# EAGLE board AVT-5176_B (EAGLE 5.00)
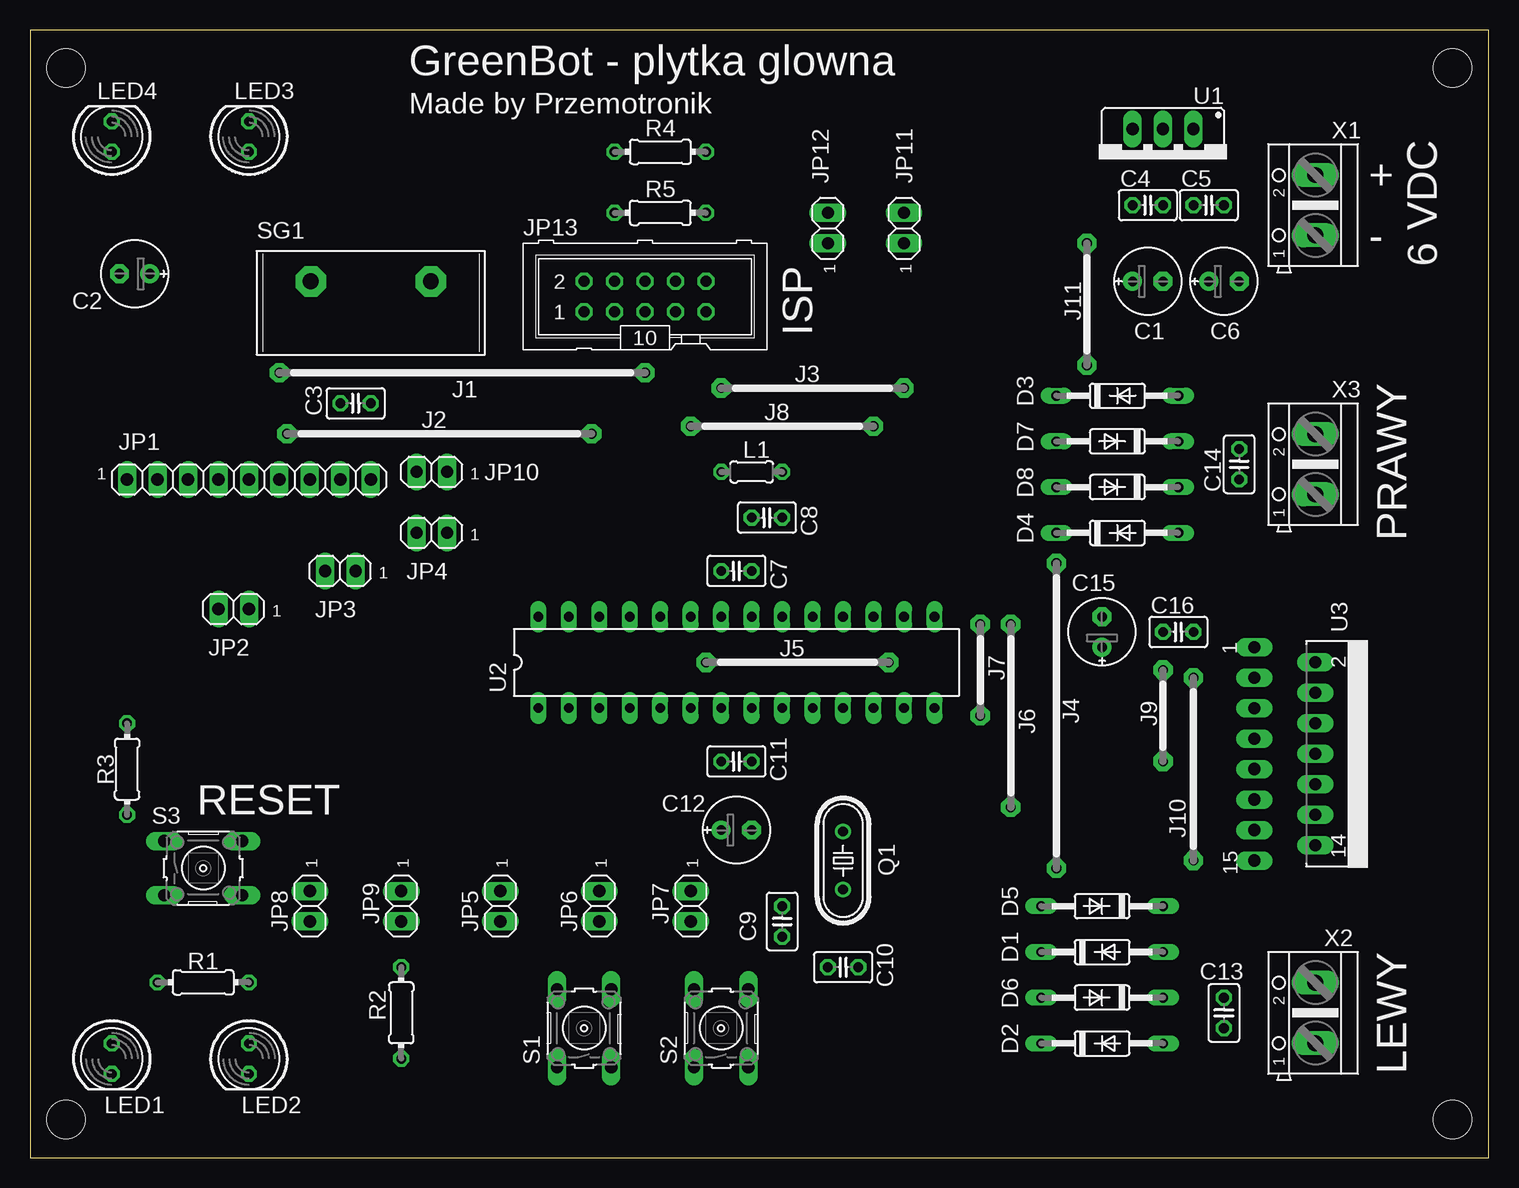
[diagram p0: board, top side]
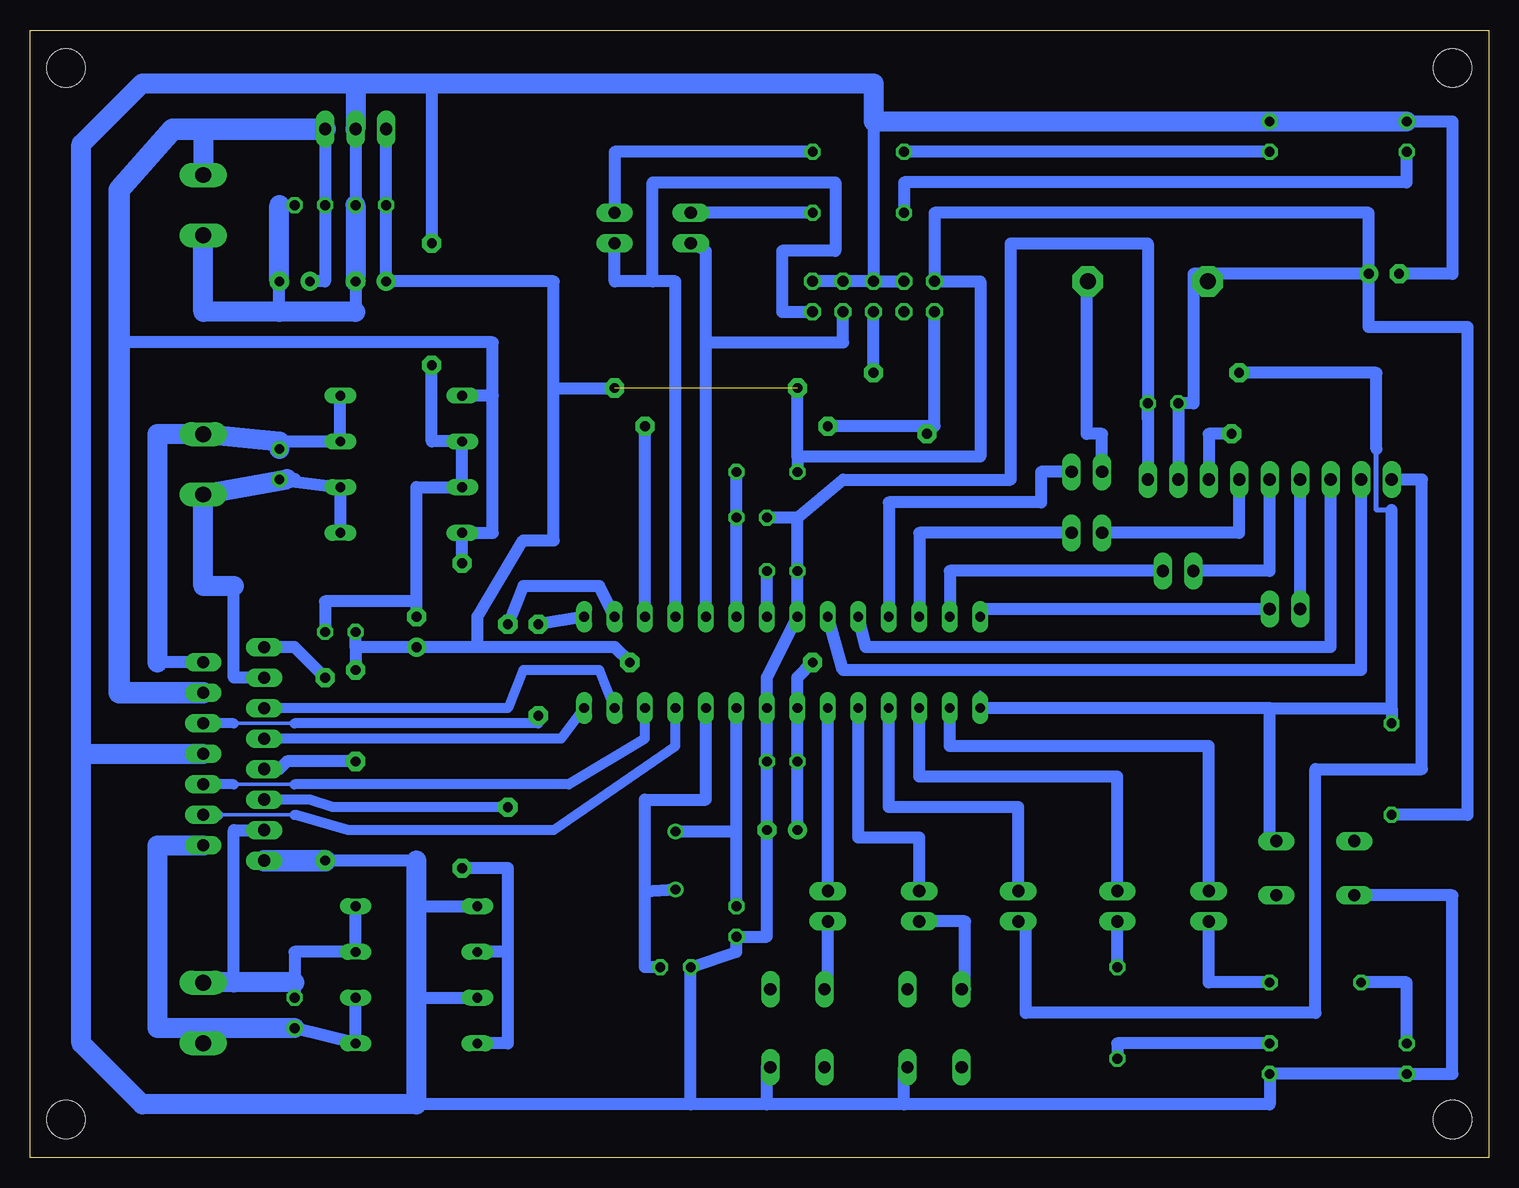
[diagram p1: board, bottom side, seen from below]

Size 121.59 x 93.97 mm. Coordinates in mm from the lower left corner, seen from the top.
Outline: 0,0 121.59,0 121.59,93.97 0,93.97 0,0
Copper layers (1*16): Top 0.035mm / dielectric 1.5mm / Bottom 0.035mm
Design rules "default": minimum track width 10mil, minimum drill 24mil, track to track 8mil, track to pad 8mil, pad to pad 8mil, via to via 8mil, smd to smd 8mil, copper to edge 40mil, drill to drill 8mil, minimum pad ring 10mil, minimum via ring 8mil, stop-mask expansion 4mil, vias tented up to drill 0mil, thermal gap 10mil
Holes 3.2 mm at 3.01,90.8 3.01,3.17 118.58,90.8 118.58,3.17

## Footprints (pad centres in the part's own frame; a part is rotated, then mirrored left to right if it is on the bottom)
E2,5-6E = drill 0.813 pad 1.575 round: + -1.27,0 | drill 0.813 pad 1.575 octagon: - 1.27,0
C025-025X050 = drill 0.813 octagon: 1 -1.27,0; 2 1.27,0
DO35-10 = drill 0.813 long: A 5.08,0; C -5.08,0
30 = drill 0.813 pad 1.6 octagon: 1 -15.24,0; 2 15.24,0
25 = drill 0.813 pad 1.6 octagon: 1 -12.7,0; 2 12.7,0
15 = drill 0.813 pad 1.6 octagon: 1 -7.62,0; 2 7.62,0
07 = drill 0.813 pad 1.6 octagon: 1 -3.81,0; 2 3.81,0
10 = drill 0.813 pad 1.6 octagon: 1 -5.08,0; 2 5.08,0
1X09 = drill 1.016 long: 1 -10.16,0; 2 -7.62,0; 3 -5.08,0; 4 -2.54,0; 5 0,0; 6 2.54,0; 7 5.08,0; 8 7.62,0; 9 10.16,0
1X02 = drill 1.016 long: 1 -1.27,0; 2 1.27,0
ML10 = drill 0.914 octagon: 1 -5.08,-1.27; 2 -5.08,1.27; 3 -2.54,-1.27; 4 -2.54,1.27; 5 0,-1.27; 6 0,1.27; 7 2.54,-1.27; 8 2.54,1.27; 9 5.08,-1.27; 10 5.08,1.27
0204/5 = drill 0.813 octagon: 1 -2.54,0; 2 2.54,0
LED5MM = drill 0.813 octagon: A -1.27,0; K 1.27,0
HC49/S = drill 0.813 round: 1 -2.413,0; 2 2.413,0
0204/7 = drill 0.813 octagon: 1 -3.81,0; 2 3.81,0
B3F-10XX = drill 1.016 long: 1 -3.251,2.261; 2 3.251,2.261; 3 -3.251,-2.261; 4 3.251,-2.261
B/C14S = drill 1.321 pad 2.54 octagon: 1 -5.004,0; 2 5.004,0
78XXS = drill 1.016 long: GND 0,-2.54; IN -2.54,-2.54; OUT 2.54,-2.54
DIL28-3 = drill 0.813 long: 1 -16.51,-3.81; 2 -13.97,-3.81; 3 -11.43,-3.81; 4 -8.89,-3.81; 5 -6.35,-3.81; 6 -3.81,-3.81; 7 -1.27,-3.81; 8 1.27,-3.81; 9 3.81,-3.81; 10 6.35,-3.81; 11 8.89,-3.81; 12 11.43,-3.81; 13 13.97,-3.81; 14 16.51,-3.81; 15 16.51,3.81; 16 13.97,3.81; 17 11.43,3.81; 18 8.89,3.81; 19 6.35,3.81; 20 3.81,3.81; 21 1.27,3.81; 22 -1.27,3.81; 23 -3.81,3.81; 24 -6.35,3.81; 25 -8.89,3.81; 26 -11.43,3.81; 27 -13.97,3.81; 28 -16.51,3.81
MULTIWATT-15 = drill 1.016 long: 1 -8.89,-7.62; 2 -7.62,-2.54; 3 -6.35,-7.62; 4 -5.08,-2.54; 5 -3.81,-7.62; 6 -2.54,-2.54; 7 -1.27,-7.62; 8 0,-2.54; 9 1.27,-7.62; 10 2.54,-2.54; 11 3.81,-7.62; 12 5.08,-2.54; 13 6.35,-7.62; 14 7.62,-2.54; 15 8.89,-7.62
AK500/2 = drill 1.321 long: 1 -2.515,0; 2 2.515,0

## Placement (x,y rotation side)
C1  100uF  [E2,5-6E]  93.18,73.02 0 top
C2  100uF  [E2,5-6E]  8.72,73.65 180 top
C3  100nF  [C025-025X050]  27.14,62.86 0 top
C4  100nF  [C025-025X050]  93.18,79.37 0 top
C5  100nF  [C025-025X050]  98.26,79.37 0 top
C6  100uF  [E2,5-6E]  99.53,73.02 0 top
C7  100nF  [C025-025X050]  58.89,48.89 180 top
C8  100nF  [C025-025X050]  61.43,53.34 180 top
C9  33pF  [C025-025X050]  62.7,19.68 90 top
C10  33pF  [C025-025X050]  67.78,15.87 0 top
C11  100nF  [C025-025X050]  58.89,33.02 180 top
C12  100uF  [E2,5-6E]  58.89,27.3 0 top
C13  100nF  [C025-025X050]  99.53,12.06 90 top
C14  100nF  [C025-025X050]  100.8,57.78 90 top
C15  100uF  [E2,5-6E]  89.37,43.81 90 top
C16  100nF  [C025-025X050]  95.72,43.81 0 top
D1  BYV26E  [DO35-10]  89.37,17.14 0 top
D2  BYV26E  [DO35-10]  89.37,9.52 0 top
D3  BYV26E  [DO35-10]  90.64,63.49 0 top
D4  BYV26E  [DO35-10]  90.64,52.06 0 top
D5  BYV26E  [DO35-10]  89.37,20.95 180 top
D6  BYV26E  [DO35-10]  89.37,13.33 180 top
D7  BYV26E  [DO35-10]  90.64,59.69 180 top
D8  BYV26E  [DO35-10]  90.64,55.88 180 top
J1  J30MM  [30]  36.03,65.4 180 top
J2  J25MM  [25]  34.12,60.32 180 top
J3  J15MM  [15]  65.24,64.13 180 top
J4  J25MM  [25]  85.56,36.82 90 top
J5  J15MM  [15]  63.97,41.27 180 top
J6  J15MM  [15]  81.75,36.82 270 top
J7  J7MM  [07]  79.21,40.63 270 top
J8  J15MM  [15]  62.7,60.95 180 top
J9  J7MM  [07]  94.45,36.82 270 top
J10  J15MM  [15]  96.99,32.38 90 top
J11  J10MM  [10]  88.1,71.11 270 top
JP1  [1X09]  18.25,56.51 0 top
JP2  [1X02]  16.98,45.72 180 top
JP3  [1X02]  25.87,48.89 180 top
JP4  [1X02]  33.49,52.06 180 top
JP5  [1X02]  39.2,20.95 270 top
JP6  [1X02]  47.46,20.95 270 top
JP7  [1X02]  55.08,20.95 270 top
JP8  [1X02]  23.33,20.95 270 top
JP9  [1X02]  30.95,20.95 270 top
JP10  [1X02]  33.49,57.15 180 top
JP11  [1X02]  72.86,77.46 90 top
JP12  [1X02]  66.51,77.46 90 top
JP13  AVR-ISP-10ML  [ML10]  51.27,71.75 0 top
L1  10uH  [0204/5]  60.16,57.15 0 top
LED1  R 5mm  [LED5MM]  6.82,8.25 270 top
LED2  G 5mm  [LED5MM]  18.25,8.25 270 top
LED3  R 5mm  [LED5MM]  18.25,85.08 90 top
LED4  G 5mm  [LED5MM]  6.82,85.08 90 top
Q1  8MHz  [HC49/S]  67.78,24.76 90 top
R1  220R  [0204/7]  14.44,14.6 180 top
R2  220R  [0204/7]  30.95,12.06 90 top
R3  1k  [0204/7]  8.09,32.38 270 top
R4  220R  [0204/7]  52.54,83.81 180 top
R5  220R  [0204/7]  52.54,78.73 0 top
S1  uSwitch  [B3F-10XX]  46.19,10.79 90 top
S2  uSwitch  [B3F-10XX]  57.62,10.79 90 top
S3  uSwitch  [B3F-10XX]  14.44,24.12 0 top
SG1  Piezzo z gen.  [B/C14S]  28.41,73.02 0 top
U1  L4940V05  [78XXS]  94.45,83.18 180 top
U2  MEGA8-P  [DIL28-3]  58.89,41.27 0 top
U3  L298  [MULTIWATT-15]  109.69,33.65 270 top
X1  ARK2  [AK500/2]  107.15,79.37 90 top
X2  ARK2  [AK500/2]  107.15,12.06 90 top
X3  ARK2  [AK500/2]  107.15,57.78 90 top

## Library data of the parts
C1-C16 L1 R1-R5 = rcl
D1-D8 = diode
J1-J11 = jumper
JP1-JP12 = pinhead
JP13 = atmel-1
LED1-LED4 = led
Q1 = crystal
S1-S3 = switch-omron
SG1 = buzzer
U1 = v-reg
U2 = atmel
U3 = st-microelectronics
X1-X3 = con-ptr500

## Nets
+5V: C1.+ C2.+ C3.1 C4.1 C15.+ C16.1 J3.1 J3.2 J5.1 J9.1 JP1.8 JP13.2 L1.1 R3.2 SG1.1 U1.OUT
GND: C1.- C2.- C3.2 C4.2 C5.2 C6.- C7.2 C8.2 C9.1 C10.1 C11.1 C12.- D5.A D6.A J10.1 J11.1 JP1.9 JP13.4 JP13.6 JP13.8 JP13.10 LED1.K LED2.K LED3.K LED4.K S1.3 S2.3 S3.3 U1.GND U2.8 U2.22 U3.8 U3.15 X1.1
N$1: JP10.2 SG1.2
N$2: C7.1 U2.21
N$3: C5.1 C6.+ D3.C D4.C J4.2 U1.IN U3.4 X1.2
N$4: C9.2 Q1.2 U2.9
N$5: C10.2 Q1.1 U2.10
N$6: JP10.1 U2.25
N$7: JP11.1 JP13.9 U2.18
N$8: LED3.A R4.2
N$9: JP8.2 R1.1
N$10: J6.1 U2.16
N$11: C8.1 L1.2 U2.20
N$12: JP1.2 U2.23
N$13: JP1.1 JP5.2
N$14: JP11.2 R4.1
N$15: J1.1 JP13.5
N$16: JP12.2 R5.2
N$17: JP1.6 JP4.2
N$18: JP1.3 U2.24
N$19: J6.2 U3.11
N$20: JP9.2 R2.2
N$21: JP1.5 JP3.2
N$22: JP1.4 JP2.2
N$23: LED4.A R5.1
N$24: LED1.A R1.2
N$25: LED2.A R2.1
N$26: J2.1 J8.2 JP13.1
N$27: JP8.1 U2.2
N$28: JP6.2 S1.2
N$29: J7.2 U3.6
N$30: JP5.1 U2.4
N$31: JP6.1 U2.5
N$32: JP9.1 U2.3
N$33: JP12.1 JP13.7 U2.19
N$34: JP7.2 S2.2
N$35: C14.1 D4.A D8.C U3.3 X3.1
N$36: C14.2 D3.A D7.C U3.2 X3.2
N$37: U2.13 U3.5
N$38: J2.2 JP1.7
N$39: J9.2 U3.9
N$40: J8.1 U2.17
N$41: C11.2 C12.+ J5.2 U2.7
N$42: D1.C D2.C J4.1
N$43: J10.2 U3.1
N$44: J1.2 R3.1 S3.2 U2.1
N$45: JP7.1 U2.6
N$46: U2.12 U3.10
N$47: JP3.1 U2.27
N$48: U2.14 U3.7
N$49: U2.11 U3.12
N$50: J7.1 U2.15
N$52: C13.2 D1.A D5.C U3.13 X2.2
N$53: C15.- C16.2 D7.A D8.A J11.2
N$55: C13.1 D2.A D6.C U3.14 X2.1
N$57: JP4.1 U2.26
N$59: JP2.1 U2.28

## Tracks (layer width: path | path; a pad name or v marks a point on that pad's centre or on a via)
+5V  (1 unrouted)
  Bottom 1.016: U1.OUT C4.1 C1.+ 77.94,73.02 77.94,64.13 | C2.+ 10,69.21 1.74,69.21 1.74,28.57 R3.2 | 94.45,42.54 C15.+ 84.29,42.54 | 84.29,42.54 84.29,45.08 80.48,51.43 77.94,51.43 77.94,64.13 | 77.94,64.13 J3.1 | 84.29,42.54 72.86,42.54 J5.1 | 94.45,42.54 J9.1 | 94.45,42.54 C16.1 | 57.62,58.41 L1.1 | 57.62,58.41 J3.2 | JP1.8 C3.1 24.6,62.86 24.6,73.02 | C2.+ 10,78.73 46.19,78.73 JP13.2 42.38,73.02 42.38,58.41 57.62,58.41 | C2.+ 24.6,73.65 24.6,73.02 | 24.6,73.02 SG1.1
GND
  Bottom 1.016: 100.8,70.48 C6.- | C1.- 94.45,70.48 | U1.GND C4.2 | 100.8,79.37 C5.2 | JP13.10 JP13.8 JP13.6 | JP13.6 JP13.4 | 48.73,4.44 18.25,4.44 LED2.K LED1.K 3.01,6.98 3.01,21.86 S3.3 | 48.73,4.44 60.16,4.44 | 60.16,4.44 66.51,4.44 | 66.51,4.44 C10.1 62.7,17.14 C9.1 60.16,18.41 C12.- C11.1 U2.8 60.16,40 U2.22 C7.2 57.62,53.34 | S1.3 48.73,7.54 48.73,4.44 | S2.3 60.16,7.54 60.16,4.44 | 51.27,86.35 JP13.6 | 57.62,53.34 C8.2 | LED4.K 3.01,86.35 3.01,73.65 C2.- | 66.51,4.44 89.37,4.44 | 89.37,20.95 D5.A | 89.37,13.33 D6.A | 89.37,24.76 J10.1 | 88.1,89.53 J11.1 | 28.41,61.59 JP1.9 | 28.41,61.59 C3.2 | 28.41,61.59 28.41,76.19 39.84,76.19 39.84,56.51 53.81,56.51 57.62,53.34
  Bottom 1.676: 89.37,24.76 89.37,20.95 89.37,13.33 89.37,4.44 112.23,4.44 117.31,9.52 117.31,33.65 | LED4.K LED3.K 51.27,86.35 51.27,89.53 88.1,89.53 94.45,89.53 | 94.45,89.53 U1.GND | 117.31,33.65 U3.8 | 117.31,33.65 117.31,84.45 112.23,89.53 94.45,89.53 | 94.45,70.48 100.8,70.48 107.15,70.48 X1.1 | C4.2 C1.- | C6.- 100.8,79.37
  Bottom 1.778: J10.1 U3.15
N$1
  Bottom 1.016: SG1.2 33.49,73.02 33.49,60.32 32.22,60.32 JP10.2
N$2
  Bottom 1.016: U2.21 C7.1
N$3
  Bottom 1.016: U1.IN C5.1 96.99,73.02 C6.+ | 83.02,63.49 83.02,52.06 D4.C J4.2 | 83.02,63.49 D3.C | 114.13,67.94 83.02,67.94 83.02,63.49
  Bottom 1.676: 107.15,85.72 X1.2
  Bottom 1.778: U3.4 114.13,38.73 114.13,67.94 114.13,80.64 109.69,85.72 107.15,85.72 U1.IN
N$4
  Bottom 1.016: C9.2 62.7,27.17 | 62.7,27.17 U2.9 | 62.7,27.17 Q1.2
N$5
  Bottom 1.016: 70.32,22.22 70.32,29.84 65.24,29.84 U2.10 | 70.32,22.22 Q1.1 | C10.2 70.32,15.87 70.32,22.22
N$6
  Bottom 1.016: U2.25 50,54.61 37.3,54.61 37.3,57.15 JP10.1
N$7
  Bottom 1.016: U2.18 67.78,73.02 69.69,73.02 | 69.69,73.02 72.86,73.02 JP11.1 | JP13.9 58.89,70.48 58.89,75.56 54.45,75.56 54.45,81.27 69.69,81.27 69.69,73.02
N$8
  Bottom 1.016: LED3.A R4.2
N$9
  Bottom 1.016: R1.1 23.33,14.6 JP8.2
N$10
  Bottom 1.016: U2.16 74.13,47.62 80.48,47.62 J6.1
N$11
  Bottom 1.016: U2.20 C8.1 L1.2
N$12
  Bottom 1.016: U2.23 53.81,40.63 10.63,40.63 JP1.2
N$13
  Bottom 1.016: JP5.2 38.57,19.68 38.57,12.06 14.44,12.06 14.44,32.38 5.55,32.38 5.55,56.51 JP1.1
N$14
  Bottom 1.016: JP11.2 72.86,83.81 R4.1
N$15
  Bottom 1.016: J1.1 JP13.5
N$16
  Bottom 1.016: R5.2 JP12.2
N$17
  Bottom 1.016: JP4.2 20.79,52.06 JP1.6
N$18
  Bottom 1.016: U2.24 51.91,42.54 13.17,42.54 JP1.3
N$19
  Bottom 0.813: U3.11 98.26,29.84 96.35,29.21 J6.2
N$20
  Bottom 1.016: R2.2 JP9.2
N$21
  Bottom 1.016: JP3.2 18.25,48.89 JP1.5
N$22
  Bottom 1.016: JP2.2 JP1.4
N$23
  Bottom 1.016: LED4.A 6.82,81.27 48.73,81.27 R5.1
N$24
  Bottom 1.016: LED1.A 6.82,14.6 R1.2
N$25
  Bottom 1.016: LED2.A 30.95,9.52 R2.1
N$26
  Bottom 1.016: 46.19,60.95 J8.2 | J2.1 46.19,60.95 | 46.19,60.95 JP13.1
N$27
  Bottom 1.016: U2.2 44.92,34.28 23.33,34.28 JP8.1
N$28
  Bottom 1.016: S1.2 43.65,14.04 43.65,19.68 JP6.2
N$29
  Bottom 0.305: 99.53,36.19 104.61,36.19
  Bottom 0.813: J7.2 79.21,36.19 99.53,36.19 | 104.61,36.19 U3.6
N$30
  Bottom 1.016: U2.4 50,29.21 39.2,29.21 JP5.1
N$31
  Bottom 1.016: U2.5 52.54,26.66 47.46,26.66 JP6.1
N$32
  Bottom 1.016: U2.3 47.46,31.75 30.95,31.75 JP9.1
N$33
  Bottom 1.016: 65.24,67.94 53.81,67.94 JP13.7 | 65.24,67.94 65.24,75.56 JP12.1 | U2.19 65.24,67.94
N$34
  Bottom 1.016: S2.2 55.08,14.04 JP7.2
N$35
  Bottom 1.016: U3.3 104.61,40 104.61,47.62 | C14.1 99.5,56.54 | 100.16,56.54 C14.1 | D4.A D8.C C14.1
  Bottom 1.676: 104.61,47.62 107.15,47.62 X3.1 100.16,56.54
N$36
  Bottom 1.016: 107.15,60.32 X3.2 | D3.A D7.C 100.8,59.69 | U3.2 110.96,41.27
  Bottom 1.676: 110.96,41.27 110.96,60.32 107.15,60.32 100.8,59.69 C14.2
N$37
  Bottom 0.813: U3.5 81.75,37.46 80.48,40.63 74.13,40.63 U2.13
N$38
  Bottom 1.016: J2.2 23.33,60.32 JP1.7
N$39
  Bottom 1.016: U3.9 100.8,32.38 100.16,33.02 J9.2
N$40
  Bottom 1.016: U2.17 J8.1
N$41
  Bottom 1.016: C12.+ C11.2 U2.7 57.62,40 J5.2
N$42
  Bottom 1.016: D2.C 81.75,9.52 81.75,17.14 | 81.75,17.14 D1.C | J4.1 81.75,24.12 81.75,17.14
N$43
  Bottom 1.016: J10.2 99.53,42.54 U3.1
N$44
  Bottom 0.406: U2.1 42.38,38.73 | 8.09,53.97 9.36,53.97 9.36,59.05
  Bottom 1.016: S3.2 18.25,26.74 18.25,37.46 | 18.25,37.46 8.09,37.46 | 8.09,37.46 R3.1 | 18.25,37.46 U2.1 | 9.36,59.05 9.36,65.4 J1.2 | 8.09,37.46 8.09,53.97
N$45
  Bottom 1.016: JP7.1 U2.6
N$46
  Bottom 0.305: 99.53,31.11 104.61,31.11
  Bottom 0.813: 104.61,31.11 U3.10 | 99.53,31.11 76.67,31.11 70.32,34.92 U2.12
N$47
  Bottom 1.016: U2.27 44.92,48.89 JP3.1
N$48
  Bottom 0.813: U3.7 77.31,34.92 U2.14
N$49
  Bottom 0.305: 99.53,28.57 105.88,28.57
  Bottom 0.813: 99.53,28.57 95.09,27.3 77.94,27.3 67.78,34.28 U2.11 | 105.88,28.57 U3.12
N$50
  Bottom 1.016: U2.15 J7.1
N$52
  Bottom 1.016: C13.2 99.53,14.6 99.53,17.14 D1.A D5.C | 107.15,14.6 X2.2 | U3.13 104.61,27.3 104.61,14.6
  Bottom 1.676: 99.53,14.6 104.61,14.6 107.15,14.6
N$53
  Bottom 1.016: 89.37,46.35 89.37,55.88 D8.A D7.A 88.1,59.69 J11.2 | 89.37,46.35 96.99,46.35 C16.2 | C15.- 89.37,46.35
N$55
  Bottom 1.016: 107.15,10.79 X2.1 | D6.C D2.A C13.1
  Bottom 1.676: U3.14 110.96,26.03 110.96,10.79 107.15,10.79 C13.1
N$57
  Bottom 1.016: U2.26 47.46,52.06 JP4.1
N$59
  Bottom 1.016: U2.28 42.38,45.72 JP2.1

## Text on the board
tPlace: GreenBot - plytka glowna | Made by Przemotronik
tNames: + | - | ISP | 6 VDC | 1 | 1 | 1 | 1 | 1 | PRAWY | 1 | 1 | RESET | 1 | 1 | 1 | 1 | 1 | LEWY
